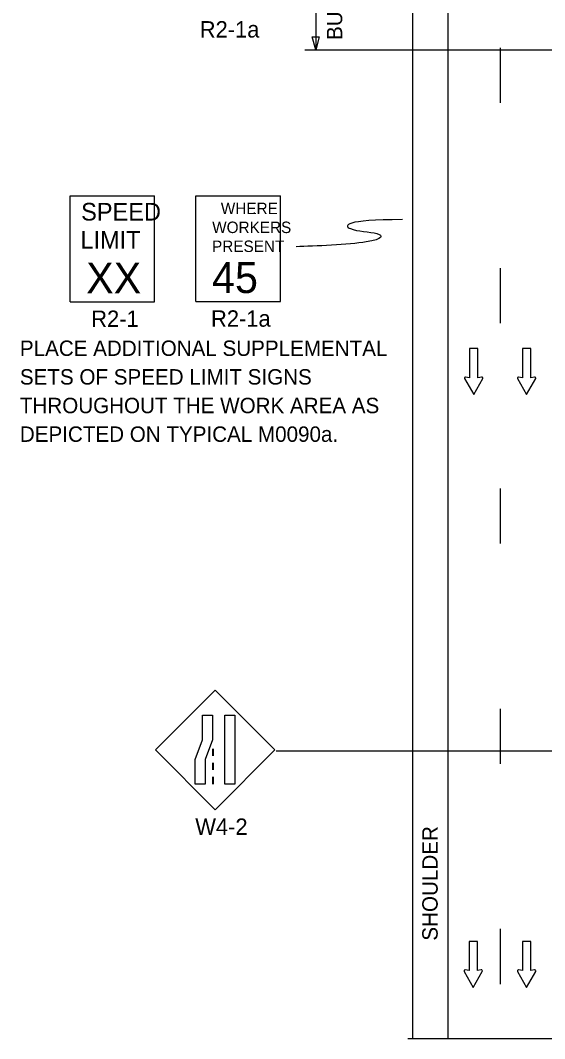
# Model space of a CAD drawing. Extents: x 16724 to 19504, y 5662 to 6979.
# Drawn here: x 16739.6 to 16977.8, y 6089 to 6551.3 of the extents above; entities that cross this region are included whole.
import ezdxf

# ---------------------------------------------------------------- set-up
doc = ezdxf.new("R2010")
doc.units = 0
for name, color, linetype in [('ALI_LEGAL_EX', 7, 'Continuous'), ('MT_SCRATCH_LEVEL_E', 7, 'Continuous'), ('PAVT_EDGE_EX', 7, 'Continuous'), ('TRAFFIC_SIGNS_PR', 7, 'Continuous'), ('TYPICAL_TEXT_DIMEN_PR', 7, 'Continuous')]:
    doc.layers.add(name, color=color, linetype=linetype)

msp = doc.modelspace()

# ---------------------------------------------------------------- linework, layer by layer
at = {"layer": 'ALI_LEGAL_EX'}
for points in [[(16957.81, 6513.81), (16957.81, 6538.81)], [(16957.81, 6413.81), (16957.81, 6438.81)], [(16957.81, 6313.81), (16957.81, 6338.81)], [(16957.81, 6213.81), (16957.81, 6238.81)], [(16957.81, 6113.81), (16957.81, 6138.81)]]:
    msp.add_lwpolyline(points, dxfattribs=at)
at = {"layer": 'MT_SCRATCH_LEVEL_E'}
for p, q in [((16947.41, 6402.27), (16943.67, 6402.27)), ((16943.67, 6402.27), (16943.67, 6389.02)), ((16947.41, 6402.27), (16943.67, 6402.27)), ((16943.67, 6402.27), (16943.67, 6389.02)), ((16947.41, 6389.02), (16947.41, 6402.27)), ((16947.41, 6389.02), (16947.41, 6402.27)), ((16971.48, 6402.27), (16967.74, 6402.27)), ((16967.74, 6402.27), (16967.74, 6389.02)), ((16971.48, 6402.27), (16967.74, 6402.27)), ((16967.74, 6402.27), (16967.74, 6389.02)), ((16971.48, 6389.02), (16971.48, 6402.27)), ((16971.48, 6389.02), (16971.48, 6402.27)), ((16941.41, 6388.65), (16945.56, 6381.41)), ((16941.41, 6388.65), (16945.56, 6381.41)), ((16943.67, 6389.02), (16941.89, 6389.33)), ((16943.67, 6389.02), (16941.89, 6389.33)), ((16945.56, 6381.41), (16949.67, 6388.65)), ((16945.56, 6381.41), (16949.67, 6388.65)), ((16949.19, 6389.33), (16947.41, 6389.02)), ((16949.19, 6389.33), (16947.41, 6389.02)), ((16965.48, 6388.65), (16969.63, 6381.41)), ((16965.48, 6388.65), (16969.63, 6381.41)), ((16967.74, 6389.02), (16965.96, 6389.33)), ((16967.74, 6389.02), (16965.96, 6389.33)), ((16969.63, 6381.41), (16973.74, 6388.65)), ((16969.63, 6381.41), (16973.74, 6388.65)), ((16973.26, 6389.33), (16971.48, 6389.02)), ((16973.26, 6389.33), (16971.48, 6389.02)), ((16947.22, 6133.16), (16943.48, 6133.16)), ((16943.48, 6133.16), (16943.48, 6119.9)), ((16947.22, 6133.16), (16943.48, 6133.16)), ((16943.48, 6133.16), (16943.48, 6119.9)), ((16947.22, 6119.9), (16947.22, 6133.16)), ((16947.22, 6119.9), (16947.22, 6133.16)), ((16971.48, 6133.16), (16967.74, 6133.16)), ((16967.74, 6133.16), (16967.74, 6119.9)), ((16971.48, 6133.16), (16967.74, 6133.16)), ((16967.74, 6133.16), (16967.74, 6119.9)), ((16971.48, 6119.9), (16971.48, 6133.16)), ((16971.48, 6119.9), (16971.48, 6133.16)), ((16943.48, 6119.9), (16941.71, 6120.22)), ((16943.48, 6119.9), (16941.71, 6120.22)), ((16949, 6120.22), (16947.22, 6119.9)), ((16949, 6120.22), (16947.22, 6119.9)), ((16967.74, 6119.9), (16965.96, 6120.22)), ((16967.74, 6119.9), (16965.96, 6120.22)), ((16973.26, 6120.22), (16971.48, 6119.9)), ((16973.26, 6120.22), (16971.48, 6119.9)), ((16941.23, 6119.53), (16945.37, 6112.29)), ((16941.23, 6119.53), (16945.37, 6112.29)), ((16945.37, 6112.29), (16949.48, 6119.53)), ((16945.37, 6112.29), (16949.48, 6119.53)), ((16965.48, 6119.53), (16969.63, 6112.29)), ((16965.48, 6119.53), (16969.63, 6112.29)), ((16969.63, 6112.29), (16973.74, 6119.53)), ((16969.63, 6112.29), (16973.74, 6119.53))]:
    msp.add_line(p, q, dxfattribs=at)
for centre, start, end in [((16941.82, 6388.87), 80.0362, 209.7731), ((16941.82, 6388.87), 80.0362, 209.7731), ((16949.26, 6388.87), 330.4248, 99.9638), ((16949.26, 6388.87), 330.4248, 99.9638), ((16965.89, 6388.87), 80.0362, 209.7731), ((16965.89, 6388.87), 80.0362, 209.7731), ((16973.33, 6388.87), 330.4248, 99.9638), ((16973.33, 6388.87), 330.4248, 99.9638), ((16941.64, 6119.76), 80.0362, 209.7731), ((16941.64, 6119.76), 80.0362, 209.7731), ((16949.08, 6119.76), 330.4248, 99.9638), ((16949.08, 6119.76), 330.4248, 99.9638), ((16965.89, 6119.76), 80.0362, 209.7731), ((16965.89, 6119.76), 80.0362, 209.7731), ((16973.33, 6119.76), 330.4248, 99.9638), ((16973.33, 6119.76), 330.4248, 99.9638)]:
    msp.add_arc(centre, 0.463, start, end, dxfattribs=at)
at = {"layer": 'PAVT_EDGE_EX'}
for p, q in [((16917.81, 6917), (16917.81, 6089.02)), ((16933.81, 6917), (16933.81, 6089.02))]:
    msp.add_line(p, q, dxfattribs=at)
at = {"layer": 'TRAFFIC_SIGNS_PR'}
for p, q in [((16762.16, 6471.55), (16800.56, 6471.55)), ((16762.16, 6423.55), (16762.16, 6471.55)), ((16800.56, 6423.55), (16800.56, 6471.55)), ((16819.36, 6471.64), (16857.76, 6471.64)), ((16819.36, 6423.64), (16819.36, 6471.64)), ((16857.76, 6423.64), (16857.76, 6471.64)), ((16762.16, 6423.55), (16800.56, 6423.55)), ((16819.36, 6423.64), (16857.76, 6423.64)), ((16828.1, 6247.26), (16800.95, 6220.11)), ((16855.25, 6220.11), (16828.1, 6247.26)), ((16800.95, 6220.11), (16828.1, 6192.96)), ((16826.85, 6220.6), (16826.85, 6217.4)), ((16827.25, 6220.6), (16827.25, 6217.4)), ((16828.1, 6192.96), (16855.25, 6220.11)), ((16826.85, 6214.2), (16826.85, 6211)), ((16827.25, 6214.2), (16827.25, 6211)), ((16826.85, 6207.8), (16826.85, 6204.6)), ((16827.25, 6207.8), (16827.25, 6204.6))]:
    msp.add_line(p, q, dxfattribs=at)
for points in [[(16826.85, 6235.85), (16826.85, 6224.67), (16823.51, 6215.78), (16823.51, 6204.6), (16819.02, 6204.6), (16819.02, 6215.78), (16822.36, 6224.67), (16822.36, 6235.85)], [(16836.99, 6235.85), (16836.99, 6204.6), (16832.5, 6204.6), (16832.5, 6235.85)]]:
    msp.add_lwpolyline(points, close=True, dxfattribs=at)
at = {"layer": 'TYPICAL_TEXT_DIMEN_PR'}
for p, q in [((16873.81, 6577.94), (16873.81, 6537.94)), ((16873.81, 6537.94), (16872.24, 6543.8)), ((16872.24, 6543.8), (16873.81, 6543.8)), ((16873.81, 6543.8), (16875.38, 6543.8)), ((16875.38, 6543.8), (16873.81, 6537.94)), ((16868.81, 6537.94), (16981.81, 6537.94)), ((17031.52, 6219.52), (16855.81, 6219.52)), ((16915.6, 6089.02), (17128.47, 6089.02))]:
    msp.add_line(p, q, dxfattribs=at)
for points, degree in [([(16845.67, 6463.74), (16845.69, 6463.78), (16845.85, 6463.83), (16846.18, 6463.88)], 2), ([(16913.27, 6460.81), (16886.5, 6460.81), (16886.5, 6455.38), (16904.59, 6455.38), (16904.59, 6450.13), (16873.13, 6448.76), (16864.97, 6448.53)], 3)]:
    msp.add_open_spline(points, degree=degree, dxfattribs=at)

# ---------------------------------------------------------------- texts
at = {"layer": 'TRAFFIC_SIGNS_PR'}
for s, height, p in [('R2-1a', 7.44, (16821.09, 6543.47)), ('SPEED', 8, (16767.19, 6460.41)), ('WHERE', 5.2, (16830.67, 6463.32)), ('WORKERS', 5.2, (16826.74, 6454.72)), ('LIMIT', 8, (16766.86, 6447.61)), ('PRESENT', 5.2, (16826.67, 6446.12)), ('XX', 14.031, (16769.47, 6427.31)), ('45', 14.031, (16826.66, 6427.49)), ('R2-1', 7.44, (16771.77, 6412.11)), ('R2-1a', 7.44, (16826.21, 6412.2)), ('PLACE ADDITIONAL SUPPLEMENTAL', 7, (16739.36, 6398.94)), ('SETS OF SPEED LIMIT SIGNS', 7, (16739.36, 6385.94)), ('THROUGHOUT THE WORK AREA AS', 7, (16739.36, 6372.94)), ('DEPICTED ON TYPICAL M0090a.', 7, (16739.36, 6359.94)), ('W4-2', 7.44, (16819.06, 6181.52))]:
    msp.add_text(s, height=height, dxfattribs=at).set_placement(p)
at = {"layer": 'TYPICAL_TEXT_DIMEN_PR'}
for s, p in [('BUFFER', (16885.84, 6542.37)), ('SHOULDER', (16929.19, 6133.49))]:
    msp.add_text(s, height=7, rotation=90, dxfattribs=at).set_placement(p)

doc.saveas('drawing.dxf')
